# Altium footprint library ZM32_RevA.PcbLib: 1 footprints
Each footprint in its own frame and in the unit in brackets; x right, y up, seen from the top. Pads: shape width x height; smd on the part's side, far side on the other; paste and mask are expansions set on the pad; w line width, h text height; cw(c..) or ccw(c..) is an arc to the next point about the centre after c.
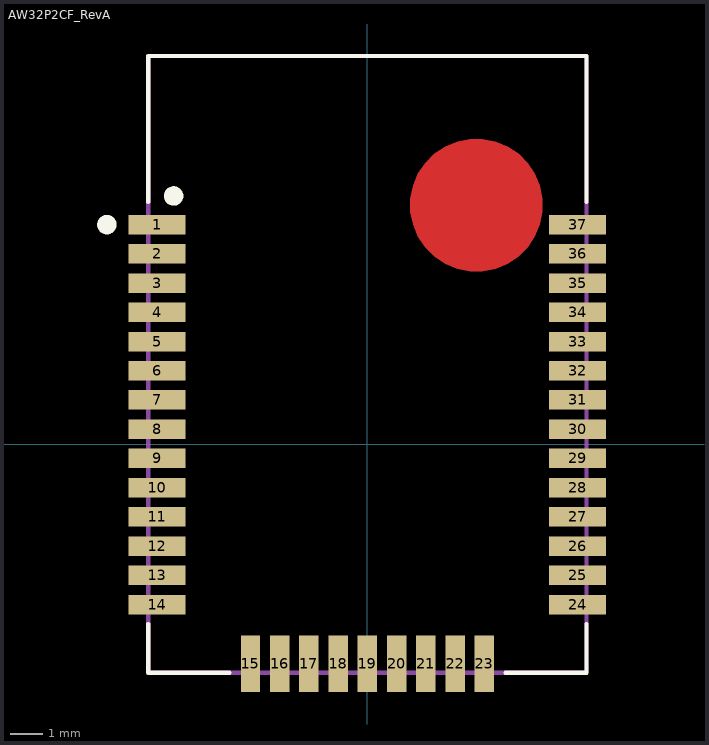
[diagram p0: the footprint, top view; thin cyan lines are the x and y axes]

## AW32P2CF_RevA [mm] "19X13.5"
height 2.5
pads (74):
  rect 1.75x0.6 smd: 1(-6.475,6.763) 2(-6.475,5.863) 3(-6.475,4.963) 4(-6.475,4.063) 5(-6.475,3.163) 6(-6.475,2.262) 7(-6.475,1.363) 8(-6.475,0.463) 9(-6.475,-0.437) 10(-6.475,-1.337) 11(-6.475,-2.237) 12(-6.475,-3.137) 13(-6.475,-4.037) 14(-6.475,-4.937) 24(6.475,-4.937) 25(6.475,-4.037) 26(6.475,-3.137) 27(6.475,-2.237) 28(6.475,-1.337) 29(6.475,-0.437) 30(6.475,0.463) 31(6.475,1.363) 32(6.475,2.263) 33(6.475,3.163) 34(6.475,4.063) 35(6.475,4.963) 36(6.475,5.863) 37(6.475,6.763)
  rect 0.6x1.75 smd: 15(-3.6,-6.763) 16(-2.7,-6.763) 17(-1.8,-6.763) 18(-0.9,-6.763) 19(0,-6.763) 20(0.9,-6.763) 21(1.8,-6.763) 22(2.7,-6.763) 23(3.6,-6.763)
  rect 1.05x0.6 on Mech15 paste-0.5 mask+0.051: ""(-6.225,-4.937) ""(-6.225,-4.037) ""(-6.225,-3.137) ""(-6.225,-2.237) ""(-6.225,-1.337) ""(-6.225,-0.437) ""(-6.225,0.463) ""(-6.225,1.363) ""(-6.225,2.263) ""(-6.225,3.163) ""(-6.225,4.063) ""(-6.225,4.963) ""(-6.225,5.863) ""(-6.225,6.763) ""(6.225,-4.937) ""(6.225,-4.037) ""(6.225,-3.137) ""(6.225,-2.237) ""(6.225,-1.337) ""(6.225,-0.437) ""(6.225,0.463) ""(6.225,1.363) ""(6.225,2.263) ""(6.225,3.163) ""(6.225,4.063) ""(6.225,4.963) ""(6.225,5.863) ""(6.225,6.763)
  rect 0.6x1.05 on Mech15 paste-0.5 mask+0.051: ""(-3.6,-6.512) ""(-2.7,-6.512) ""(-1.8,-6.512) ""(-0.9,-6.512) ""(0,-6.512) ""(0.9,-6.512) ""(1.8,-6.512) ""(2.7,-6.512) ""(3.6,-6.512)
Top Layer:
  pour cut-out: 1.327,7.364 1.327,7.164 1.405,6.772 1.558,6.402 1.781,6.069 2.064,5.786 2.397,5.564 2.766,5.41 3.159,5.332 3.359,5.332 3.559,5.332 3.952,5.41 4.322,5.564 4.655,5.786 4.938,6.069 5.16,6.402 5.313,6.772 5.391,7.164 5.391,7.364 5.391,7.564 5.313,7.957 5.16,8.327 4.938,8.66 4.655,8.943 4.322,9.165 3.952,9.318 3.559,9.396 3.359,9.396 3.159,9.396 2.766,9.318 2.397,9.165 2.064,8.943 1.781,8.66 1.558,8.327 1.405,7.957 1.327,7.564
Top Overlay:
  circle w0.3: c-5.969,7.645 r0.15
  circle w0.3: c-8.024,6.763 r0.15
  lines w0.127: -6.75,-5.537 -6.75,-7.037 -4.25,-7.037 ; -6.75,7.462 -6.75,11.963 6.75,11.963 6.75,7.462 ; 4.25,-7.037 6.75,-7.037 6.75,-5.537
Mechanical 15:
  lines w0.127: -6.75,-7.037 -6.75,11.963 6.75,11.963 6.75,-7.037 -6.75,-7.037
  text "core board test point" at -4.242,8.712 h0.51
